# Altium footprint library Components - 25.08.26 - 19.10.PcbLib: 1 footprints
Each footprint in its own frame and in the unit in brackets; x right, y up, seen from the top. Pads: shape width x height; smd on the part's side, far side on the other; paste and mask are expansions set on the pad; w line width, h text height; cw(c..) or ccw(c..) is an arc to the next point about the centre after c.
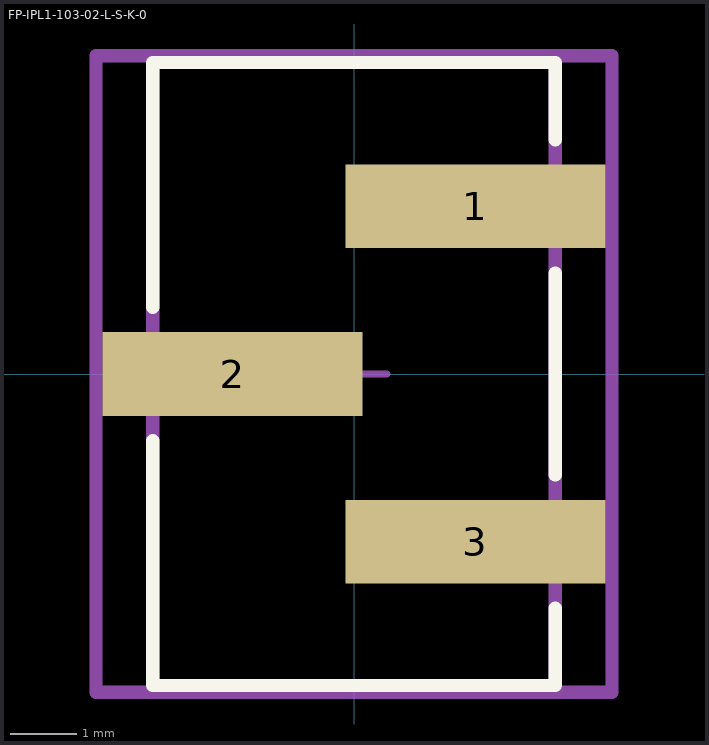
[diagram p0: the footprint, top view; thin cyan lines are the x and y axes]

## FP-IPL1-103-02-L-S-K-0 [mm]
pads (3):
  rect 3.94x1.27 smd paste+0 mask+0: 1(1.84,2.54) 2(-1.84,0) 3(1.84,-2.54)
Top Overlay:
  lines w0.2: -3.05,-1.01 -3.05,-4.72 3.05,-4.72 3.05,-3.55 ; -3.05,1.01 -3.05,4.72 3.05,4.72 3.05,3.55 ; 3.05,-1.53 3.05,1.53
Top Assembly:
  lines w0.2: -3.91,-4.82 -3.91,4.82 3.91,4.82 3.91,-4.82 -3.91,-4.82
  text ".Designator" at 0,0 h1
Top 3D Body:
  lines w0.2: -3.05,-4.72 -3.05,4.72 3.05,4.72 3.05,-4.72 -3.05,-4.72
Top Courtyard:
  lines w0.2: -3.91,-4.82 -3.91,4.82 3.91,4.82 3.91,-4.82 -3.91,-4.82
Top Component Center:
  lines w0.1: -0.5,0 0.5,0 ; 0,-0.5 0,0.5
3D body "Conn_Samtec_IPL1-103-02-L-S-K_eec.STEP": height 0.25, standoff 0, extent -3.91,-4.82 3.91,4.82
